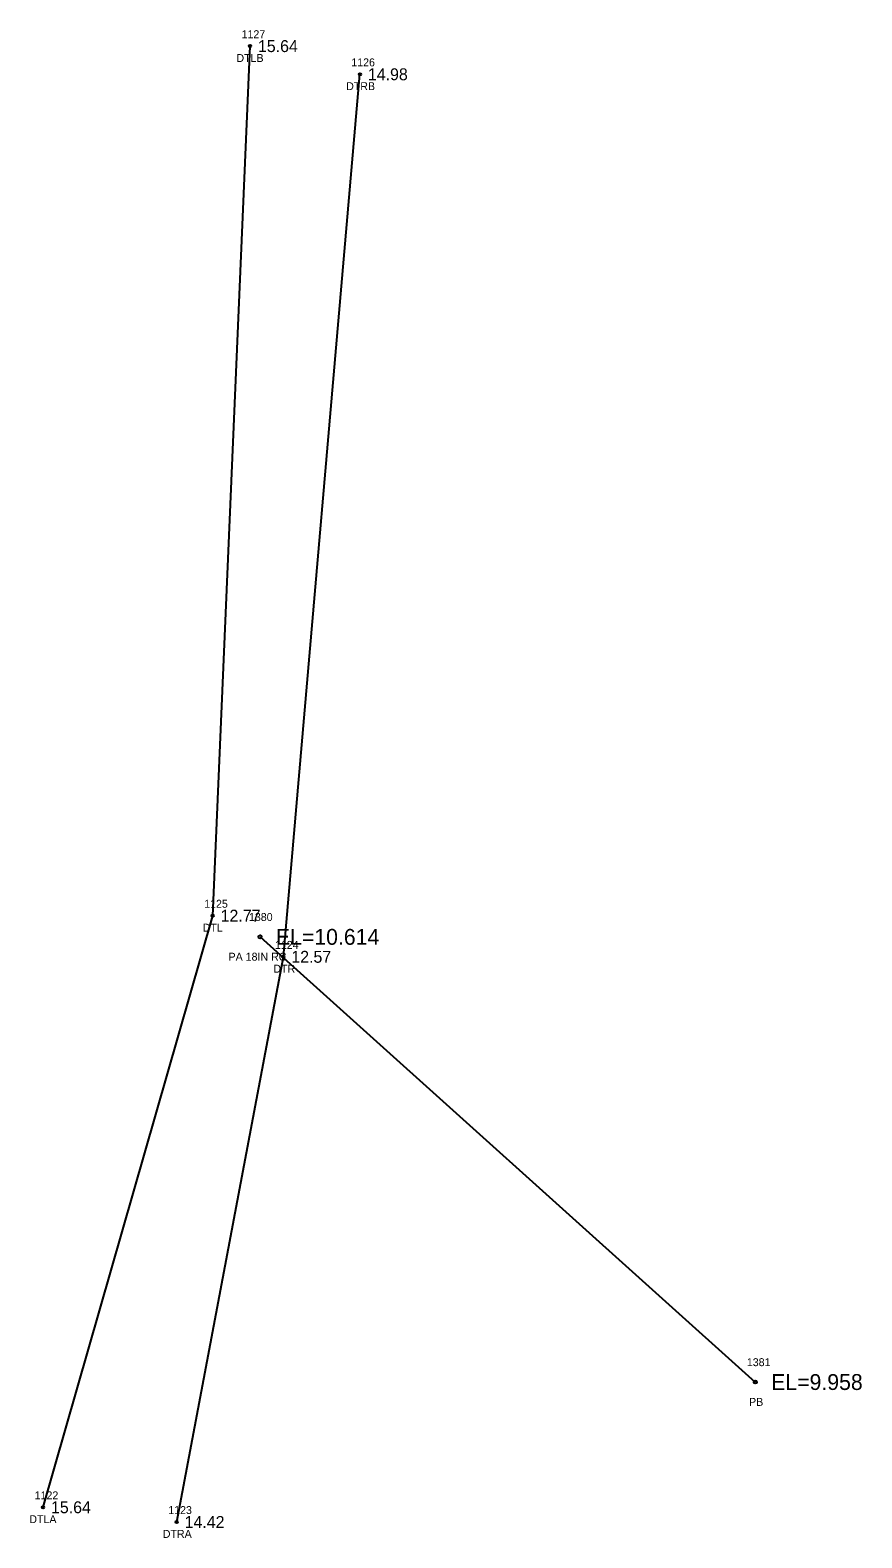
# Model space of a CAD drawing. Extents: x 2072307 to 2072993, y 127574 to 129736.
# Drawn here: x 2072664.9 to 2072769.6, y 129545.9 to 129735.9 of the extents above; entities that cross this region are included whole.
import ezdxf

# ---------------------------------------------------------------- set-up
doc = ezdxf.new("R2010")
doc.units = 0
for name, color, linetype in [('RD_EX_DR_Pipe', 7, 'Continuous'), ('RD_EX_DR_Pipe_txCode', 7, 'Continuous'), ('RD_EX_H2O', 7, 'Continuous'), ('RD_EX_H2O_txCode', 7, 'Continuous'), ('RD_EX_TX_H2O_ELEV', 7, 'Continuous'), ('RD_SMD_Locator', 7, 'Continuous'), ('RD_TX_Pipe_ElevEX', 7, 'Continuous')]:
    doc.layers.add(name, color=color, linetype=linetype)

msp = doc.modelspace()

# ---------------------------------------------------------------- linework, layer by layer
at = {"layer": 'RD_EX_DR_Pipe'}
msp.add_line((2072693.83, 129621.65), (2072756.17, 129565.57), dxfattribs=at)
at = {"layer": 'RD_EX_H2O'}
for points in [[(2072666.52, 129549.79), (2072687.87, 129624.32), (2072692.57, 129733.87)], [(2072683.34, 129547.94), (2072696.77, 129619.14), (2072706.41, 129730.32)]]:
    msp.add_lwpolyline(points, dxfattribs=at)
at = {"layer": 'RD_SMD_Locator'}
for centre, radius in [((2072692.57, 129733.87), 0.15), ((2072706.41, 129730.32), 0.15), ((2072687.87, 129624.32), 0.15), ((2072693.83, 129621.65), 0.2), ((2072696.77, 129619.14), 0.15), ((2072756.17, 129565.57), 0.2), ((2072666.52, 129549.79), 0.15), ((2072683.34, 129547.94), 0.15)]:
    msp.add_circle(centre, radius, dxfattribs=at)

# ---------------------------------------------------------------- texts
at = {"layer": 'RD_EX_DR_Pipe_txCode'}
for s, p in [('1380', (2072692.44, 129623.65)), ('PA 18IN RC', (2072689.87, 129618.65)), ('1381', (2072755.11, 129567.57)), ('PB', (2072755.39, 129562.57))]:
    msp.add_text(s, height=1, dxfattribs=at).set_placement(p)
at = {"layer": 'RD_EX_H2O_txCode'}
for s, p in [('1127', (2072691.51, 129734.87)), ('DTLB', (2072690.86, 129731.87)), ('1126', (2072705.32, 129731.32)), ('DTRB', (2072704.67, 129728.32)), ('1125', (2072686.8, 129625.32)), ('DTL', (2072686.62, 129622.32)), ('1124', (2072695.71, 129620.14)), ('DTR', (2072695.51, 129617.14)), ('1122', (2072665.46, 129550.79)), ('DTLA', (2072664.79, 129547.79)), ('1123', (2072682.28, 129548.94)), ('DTRA', (2072681.59, 129545.94))]:
    msp.add_text(s, height=1, dxfattribs=at).set_placement(p)
at = {"layer": 'RD_EX_TX_H2O_ELEV'}
for s, p in [('15.64', (2072693.57, 129733.12)), ('14.98', (2072707.41, 129729.57)), ('12.77', (2072688.87, 129623.57)), ('12.57', (2072697.77, 129618.39)), ('15.64', (2072667.52, 129549.04)), ('14.42', (2072684.34, 129547.19))]:
    msp.add_text(s, height=1.5, dxfattribs=at).set_placement(p)
at = {"layer": 'RD_TX_Pipe_ElevEX'}
for s, p in [('EL=10.614', (2072695.83, 129620.65)), ('EL=9.958', (2072758.17, 129564.57))]:
    msp.add_text(s, height=2, dxfattribs=at).set_placement(p)

doc.saveas('drawing.dxf')
